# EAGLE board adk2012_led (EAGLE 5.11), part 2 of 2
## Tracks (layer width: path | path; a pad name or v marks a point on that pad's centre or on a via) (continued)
GND  (via drill 0.3) (continued)
  Top 0.508: v106.88,41.86 114.12,41.86 115.01,42.75 120.22,42.75 121.11,43.64 121.11,45.29 | 34.96,56.34 C20.2 33.52,56.49 C19.2 33.22,52.91 32.72,52.4 29.54,52.4 | 29.54,52.4 29.03,52.91 29.03,54.81 | 29.03,54.81 29.03,55.91 U10.10 29.03,55.95 | U10.11 29.81,54.96 29.67,54.81 29.03,54.81 | U10.7 26.49,57.23 25.73,56.46 25.13,56.46 C22.2 25.1,55.19 25.6,54.69 28.91,54.69 29.03,54.81 | U7.2 9.35,68.53 9.73,68.15 11.51,68.15 12.4,69.04 C23.2 12.41,69.93 | 9.47,53.42 8.97,53.92 U8.7 8.97,57.73 8.52,58.18 C26.2 | 9.47,53.42 11.38,53.42 12.01,54.05 12.01,54.77 C24.2 12.33,54.71 C25.2 | C30.2 87.83,34.75 88.34,34.24 v88.34,30.56 | C28.2 54.24,75.56 52.35,75.56 52.02,75.9 52.02,78.31 53.29,79.58 53.99,80.28 J1.6 53.99,89.42 v54.05,89.48 | v54.05,89.48 53.99,88.66 | v29.54,43 29.54,52.4 | v9.47,47.57 9.47,48.21 9.47,53.42 | J1.1 58.99,89.22 59,89.23 54.31,89.23 v54.05,89.48 | 128.6,80.85 128.6,79.45 129.43,78.63 130,78.63 132.22,78.63 132.47,78.88 C35.2 134.1,79.17 C36.2 | 128.6,80.85 U13.4 | 128.6,80.85 127.58,80.85 127.08,81.36 127.08,82.63 125.93,83.77 122.73,83.77 JP1.7 | C15.2 13.32,90.35 | C42.2 172.61,26.68 v172.29,26.37 | v0.84,70.43 1.98,70.43 v3.51,71.96 | v5.28,71.96 5.28,71.58 6.3,70.56 U7.EP
  Top 0.762: v183.21,41.73 183.21,43.03 183.24,43.03 C6.2 | v194.64,32.08 192.48,32.08 | 192.48,32.08 192.38,32.08 | v159.46,42.62 R1.1 | 183.46,26.24 v183.46,25.35 v182.58,25.35 183.46,26.24 | 183.46,26.24 v183.46,30.3 183.46,32.08 183.72,32.33 C4.2 | JP4.4 106.17,37.34 v106.88,38.05 | 15.2,90.98 15.84,91.62 17.88,91.62 C31.2 17.86,91.64 | 192.48,32.08 C8.2 | C10.2 192.86,43.89 193.12,43.89 v194.39,42.62
  Top 1.016: JP4.4 104.55,30.48 v104.47,30.56 | JP7.35 JP7.36 181.64,76.2 v181.69,76.15 | v121.87,88.34 122.68,87.53 JP1.7 122.63,83.77 121.23,83.77 120.14,82.68 JP1.6 | v161.87,36.65 161.87,34.5 C43.2 C44.2 161.81,26.81 v162.26,26.37 v163.14,26.37 v161.37,26.37
  Bottom 0.254: v194.39,42.62 194.13,42.88 191.08,42.88 190.32,43.64 190.32,50.62 v190.2,50.75 | v122,47.57 123.01,47.57 v124.28,46.3 | v98.88,48.08 98.88,46.69 100.03,45.54 105.49,45.54 106.25,44.78 v106.88,44.78 | v9.86,94.18 U11.EP@6
  Bottom 0.381: v47.83,54.18 43.64,54.18 43,53.54 v41.22,53.54
  Bottom 0.406: 193.62,94.06 196.16,94.06 | 196.16,94.06 198.07,94.06 198.32,93.8 U9.2 | 196.16,94.06 C27.2
  Bottom 0.508: v88.34,30.56 88.21,30.59 82.94,30.53 | 54.81,94.31 54.05,93.55 v54.05,89.48 | v29.54,43 29.54,43.03 29.56,42.79 | v9.47,47.57 9.47,47.32 9.49,47.45 | 0.84,89.36 v2.24,89.36 | v3.51,71.96 v5.28,71.96
  Bottom 0.762: 180.67,94.06 180.67,94.31 | 180.67,94.31 193.37,94.31 193.62,94.06 | 206.71,87.07 207.59,86.18 207.59,32.08 204.55,29.03 | 54.81,94.31 121.87,94.31 180.67,94.31 | v183.46,30.3 183.46,41.48 v183.21,41.73 | v194.39,42.62 194.64,42.37 v194.64,32.08 194.64,29.03 190.96,25.35 v183.46,25.35 v182.58,25.35 176.61,25.35 175.59,26.37 | v161.87,36.65 161.62,36.65 159.46,38.81 v159.46,42.62 | v106.88,44.78 v106.88,41.86 v106.88,38.05
  Bottom 0.889: 193.62,94.06 193.62,91.39 | 9.49,47.45 0.84,49.48 v0.84,70.43 0.84,89.36 0.84,94.18 v9.86,94.18 | 121.87,94.31 v121.87,88.34 | 180.67,88.72 180.67,94.06
  Bottom 1.016: v181.69,76.15 181.69,82.63 181.56,82.75 181.56,87.83 180.67,88.72 | 193.62,91.39 197.94,87.07 206.71,87.07 | 9.49,47.45 29.56,42.79 30.43,42.59 82.94,30.53 104.24,30.53 v104.47,30.56 108.66,26.37 v161.37,26.37 v162.26,26.37 v163.14,26.37 v172.29,26.37 175.59,26.37 | 204.55,29.03 194.64,29.03
  other vias: 6.68,92.15 6.68,94.18 30.81,94.18 13.03,94.18 16.21,94.18 19.38,94.18 23.06,94.18 27.25,94.18 9.86,92.15 23.06,86.69 27.25,86.69 30.81,86.69
  pour Top (isolate 0.762): 52.78,85.42 60.27,85.42 60.27,89.74 52.78,89.74
  pour Bottom (isolate 0.381, no thermals): 8.97,87.96 6.17,90.75 6.17,94.44 6.3,94.56 34.87,94.56 34.87,87.45 33.73,86.18 15.7,86.18 14.05,87.96
  pour Top (isolate 0.381, no thermals): 6.3,94.69 6.3,90.88 10.24,86.94 14.94,86.94 15.7,86.18 33.73,86.18 34.87,87.45 34.87,94.69
INT  (via drill 0.3)
  Top 0.254: U14.15 122.39,50.13 123.39,51.13 126.7,51.13 128.47,49.35 v131.78,49.35 133.05,49.35 133.43,48.97 133.43,48.18 R41.1 | U12.15 53.66,71.82 v52.91,71.07 | v201.12,90.5 201.12,88.21 207.21,82.12 207.21,54.05 v206.45,53.29 | v198.32,53.29 191.21,53.29 189.31,55.19 186.51,55.19 185.62,54.31 183.72,54.31 181.69,52.27 181.69,51.77 180.72,50.8 JP7.16 177.85,50.88 v174.83,50.88 | v53.67,41.1 53.67,40.46 75.01,35.64 84.15,35.64 84.91,34.87 v84.91,33.35 | v133.93,28.78 v133.93,34.87 v133.93,36.4
  Bottom 0.254: v174.83,50.88 174.83,38.05 171.65,34.87 v133.93,34.87 | v52.91,71.07 57.23,66.75 57.23,48.72 53.67,45.16 v53.67,41.1 | v206.45,53.29 v198.32,53.29 | v84.91,33.35 85.04,33.22 106.63,33.22 111.33,28.52 122.25,28.52 122.5,28.78 v133.93,28.78 | v133.93,36.4 133.93,47.19 v131.78,49.35 | U9.4 200.52,91.1 v201.12,90.5
MOSI  (via drill 0.3)
  Top 0.254: U1.32 157.64,47.11 158.06,46.69 163.91,46.69 166.19,44.4 v179.65,44.4 | JP7.32 181.86,71.12 v181.94,71.2
  Bottom 0.254: v181.94,71.2 181.94,60.02 183.21,58.75 183.21,54.43 179.65,50.88 v179.65,44.4
N$1  (via drill 0.3)
  Top 0.254: U1.25 153.9,46.46 152.86,45.42 v152.86,44.91 | U2.32 108.24,48.5 109.68,47.07 v109.68,46.56
  Bottom 0.254: v152.86,44.91 152.86,39.32 149.3,35.64 130.76,35.64 129.87,34.75 125.68,34.75 124.66,35.76 111.71,35.76 109.68,37.8 v109.68,46.56
N$2
  Top 0.254: R2.2 101.8,48.08 101.8,47.7 102.69,46.81 103.84,46.81 104.72,47.7 104.72,48.49 U2.27
N$3
  Top 0.254: R3.2 188.42,37.88 188.42,36.78 188.63,36.57 D65.C 188.67,35.85 188.67,35.26 188.48,35.06 Q1.1 188.56,34.11 189.31,34.11 189.67,33.75 C3.2
N$5
  Top 0.254: U1.27 154.9,45.81 154.64,45.54 154.64,43.55 155.56,42.62 R1.2
N$6
  Top 0.254: C5.2 189.62,44.97 189.31,45.29 188.82,45.29 Q2.1 188.48,46.49 188.67,46.69 188.67,47.28 D66.C 188.67,47.36 188.67,48.21 188.27,48.62 R5.2
N$7
  Top 0.254: R7.2 197.05,37.88 197.05,36.91 197.26,36.7 D67.C 197.31,35.85 197.31,35.26 197.11,35.06 Q3.1 197.2,34.11 197.94,34.11 198.31,33.75 C7.2
N$8
  Top 0.254: U10.12 30.61,54.87 30.05,54.31 30.05,53.71 C21.1
N$9
  Top 0.254: U10.13 31.41,54.72 31.7,54.43 31.7,53.71 C21.2
N$11
  Top 0.254: C22.1 25.69,58.08 26.24,58.62 27.32,58.62 U10.6
N$12
  Top 0.254: R9.2 196.9,48.62 197.31,48.21 197.31,47.36 D68.C 197.26,46.77 197.05,46.56 197.05,45.69 Q4.1 197.33,45.42 197.94,45.42 198.39,44.97 C9.2
N$13
  Top 0.254: R11.1 6.68,83.39 6.43,83.64 6.43,88.98 6.74,89.29 U11.3
N$14
  Top 0.254: U11.4 7.61,88.64 7.32,88.34 7.32,85.59 R12.1
N$15
  Top 0.254: R11.2 C17.1
N$16
  Top 0.254: R12.2 C18.1
N$17  (via drill 0.3)
  Top 0.254: U12.14 52.71,72.27 v52.27,71.83 | v52.78,40.46 52.78,40.08 74.88,35 81.48,35 | 81.48,35 83.39,35 v83.77,34.62 | U15.5 88.93,35.69 v89.36,35.26 | R46.1 81.55,34.94 81.48,35
  Bottom 0.254: v52.27,71.83 52.27,70.69 56.59,66.37 56.59,48.97 52.78,45.16 v52.78,40.46 | v89.36,35.26 84.4,35.26 v83.77,34.62
N$18
  Top 0.381: U11.8 11.72,90.59 12.01,90.88 12.01,91.64 13.41,93.04 20.52,93.04 21.45,92.11 FB5.1
N$19  (via drill 0.3)
  Top 0.254: 80.47,36.53 74.12,36.53 54.56,40.84 v54.56,41.73 | 80.47,36.53 U15.4 | v53.42,74.24 53.92,74.24 54.56,73.61 55.16,73.61 U12.11 | 80.47,36.53 R45.1
  Bottom 0.254: v54.56,41.73 54.56,45.03 57.86,48.34 57.86,67.26 53.42,71.7 v53.42,74.24
N$20
  Top 0.381: U11.5 11.72,88.64 12.9,87.45 15.7,87.45 16.71,86.44 19.89,86.44 21.45,88 FB6.1
N$21
  Top 0.254: J1.2 57.99,83.14 57.35,82.5 57.35,81.36 58.75,79.96 58.77,78.31 R23.1
  Top 0.406: J1.2 57.99,87.04 57.38,87.66 55.6,87.66 54.97,87.02 54.97,85.52 J1.5
N$22
  Top 0.254: J1.3 56.99,83.41 56.46,82.88 R24.1
N$23  (via drill 0.3)
  Top 0.254: U12.9 56.27,74.84 C28.1 55.58,75.53 55.58,76.53 | FB1.1 55.03,77.08 55.58,76.53 | v55.96,76.91 55.58,76.53 | v52.27,74.24 52.27,73.12 R13.2
  Bottom 0.254: v55.96,76.91 54.43,76.91 52.27,74.75 v52.27,74.24
N$24
  Bottom 0.406: U9.3 198.97,92.39 199.21,92.15 D69.2
N$25
  Top 0.254: J1.4 55.99,84.06 55.07,83.13 R25.1
N$26
  Top 0.254: U12.12 54.12,73.17 54.05,73.1 R13.1
N$27
  Top 0.254: U14.9 120.8,46.62 121.11,46.3 C29.1 | R26.2 126.82,49.35 127.97,48.21 130,48.21 130.51,47.7 130.51,46.81 130.12,46.43 127.97,46.43 127.2,47.19 126.23,47.19 FB2.1
  Top 0.305: FB2.1 125.59,47.15 125.17,47.57 123.25,47.57 122.31,46.64 C29.1
N$28
  Top 0.254: U12.5 58.27,75.92 58.75,76.4 R23.2
N$29
  Top 0.254: U12.7 57.17,78.11 55.07,80.21 R25.2
N$30
  Top 0.254: U12.6 57.62,79.06 56.46,80.21 R24.2
N$32
  Top 0.508: J2.2 39.95,86.53 39.95,86.82 | 39.95,86.82 TP2.TP | 39.95,86.82 39.95,88.6 39.45,89.1 32.4,89.1 31.38,90.12 27,90.12 25.54,88.66 C33.1 23.6,88.66 FB6.2
N$33
  Top 0.254: U14.12 122.94,48.78 123.52,49.35 R26.1
N$34  (via drill 0.3)
  Top 0.254: U14.14 122.57,49.68 123.52,50.62 126.31,50.62 128.22,48.72 v130.63,48.72 | v113.36,40.34 113.11,40.08 97.36,40.08 96.22,38.94 91.26,38.94 89.87,40.34 U15.8 88.34,40.34 87.96,40.72 R44.1
  Bottom 0.254: v130.63,48.72 130.63,36.4 129.62,35.38 125.68,35.38 124.79,36.27 113.87,36.27 113.36,36.78 v113.36,40.34
N$35  (via drill 0.3)
  Top 0.254: U14.11 123.13,48.33 123.27,48.34 126.95,48.34 127.97,47.32 v129.74,47.32 | v114,39.57 97.49,39.57 96.34,38.43 90.75,38.43 90.12,39.07 U15.7 88.09,39.07 86.06,41.1 R43.1
  Bottom 0.254: v129.74,47.32 129.74,36.4 129.24,35.89 125.81,35.89 124.92,36.78 114.38,36.78 114,37.16 v114,39.57
N$36
  Top 0.254: U12.4 58.82,73.17 59,73.36 59,75.77 59.39,76.15 60.15,76.15 60.4,76.4 R22.2
N$37  (via drill 0.3)
  Top 0.254: v58.24,82.12 60.4,79.96 R22.1 60.4,78.31
  Bottom 0.254: P1.P$1 50.37,82.12 v58.24,82.12
  pour Bottom (isolate 1.016, no thermals): 50.37,83.39 39.95,83.39 39.95,73.1 50.37,73.1
N$38  (via drill 0.3)
  Top 0.254: v51.77,90.37 52.27,90.88 60.15,90.88 61.42,89.61 61.42,75.25 61.05,74.88 R21.1
  Bottom 0.254: P2.P$1 38.05,82.88 39.83,84.66 50.75,84.66 51.77,85.67 v51.77,90.37
  pour Bottom (isolate 1.016, no thermals): 37.8,83.39 27.38,83.39 27.38,73.1 37.8,73.1
N$39
  Top 0.254: U12.3 59,72.72 59.51,73.23 59.51,74.51 R21.2
N$40
  Top 0.254: U12.2 59.43,72.27 R20.2
N$41
  Top 0.254: U12.16 54.03,71.17 52.78,69.93 R14.2
N$42  (via drill 0.3)
  Top 0.254: v79.71,48.97 93.8,48.97 96.85,45.92 101.68,45.92 103.96,43.64 113.23,43.64 114.76,45.16 R36.1
  Bottom 0.254: P12.P$1 83.26,75.01 79.71,71.45 v79.71,48.97
  pour Bottom (isolate 0.254, no thermals): 94.95,84.66 84.53,84.66 84.53,74.37 94.95,74.37
N$43  (via drill 0.3)
  Top 0.254: U14.16 121.25,51.01 121.62,51.38 v122.5,51.38 | v124.79,44.78 122.38,44.78 122.12,44.53 R27.2
  Bottom 0.254: v122.5,51.38 124.79,51.38 125.04,51.13 125.04,45.03 v124.79,44.78
N$44  (via drill 0.3)
  Top 0.254: v186.39,30.68 186.39,24.21 184.1,21.92 176.48,21.92 175.72,22.68 132.79,22.68 128.6,26.87 v128.6,36.65 | R27.1 122.12,42.24 123.01,41.35 v128.6,41.35
  Bottom 0.254: P21.P$1 188.16,55.58 186.39,53.8 v186.39,30.68 | v128.6,36.65 v128.6,41.35
  pour Bottom (isolate 0.254, no thermals): 187.66,69.42 198.07,69.42 198.07,59.13 187.66,59.13
N$45
  Top 0.254: U14.5 118.8,47.93 117.42,46.56 117.42,45.42 117.17,45.16 R36.2
N$46  (via drill 0.3)
  Top 0.254: v77.8,47.96 93.8,47.96 96.47,45.29 101.55,45.29 103.71,43.13 113.74,43.13 114.63,44.02 116.92,44.02 117.62,44.72 R37.1
  Bottom 0.254: P11.P$1 71.96,75.01 73.1,73.86 75.64,73.86 77.8,71.7 v77.8,47.96
  pour Bottom (isolate 0.254, no thermals): 72.59,84.66 62.18,84.66 62.18,74.37 72.59,74.37
N$47  (via drill 0.3)
  Top 0.254: v76.66,46.94 93.8,46.94 96.22,44.53 101.55,44.53 103.45,42.62 114,42.62 114.76,43.38 119.46,43.38 119.84,43.76 R38.1
  Bottom 0.254: v76.66,46.94 76.66,55.19 72.09,59.77 P10.P$1
  pour Bottom (isolate 0.254, no thermals): 72.59,69.42 62.18,69.42 62.18,59.13 72.59,59.13
N$48
  Top 0.254: U14.7 119.9,45.5 R38.2
N$49
  Top 0.254: U14.6 119.45,47.06 119.33,46.94 118.57,46.94 118.31,46.69 R37.2
N$50
  Top 0.254: U14.4 118.24,48.78 117.93,48.46 117.93,47.7 117.04,46.81 R35.2
N$51  (via drill 0.3)
  Top 0.254: v81.61,49.86 93.8,49.86 97.1,46.56 101.93,46.56 104.34,44.15 111.96,44.15 114.63,46.81 R35.1
  Bottom 0.254: P13.P$1 82.63,57.35 82.63,50.88 v81.61,49.86
  pour Bottom (isolate 0.254, no thermals): 94.82,69.42 84.4,69.42 84.4,59.13 94.82,59.13
N$52  (via drill 0.3)
  Top 0.254: v114,48.59 R34.1
  Bottom 0.254: P14.P$1 114.25,73.86 108.15,67.77 108.15,64.21 112.47,59.89 112.47,58.75 114,57.23 v114,48.59
  pour Bottom (isolate 0.254, no thermals): 124.16,84.66 113.74,84.66 113.74,74.37 124.16,74.37
N$53
  Top 0.254: U14.3 117.93,49.23 117.3,48.59 R34.2
N$54
  Top 0.508: P9.P$1 R14.1
N$55
  Top 0.254: U12.1 58.76,71.82 59.26,71.32 R19.2
N$56
  Top 0.254: U12.20 57.89,71.17 59.89,69.16 R18.2
N$57
  Top 0.254: U12.19 57.17,70.49 58.12,69.55 R17.2
N$58  (via drill 0.3)
  Top 0.254: v53.54,62.94 53.54,63.58 56.34,66.37 R16.1
  Bottom 0.254: P7.P$1 39.45,58.88 50.75,58.88 52.27,60.4 52.27,62.43 52.78,62.94 v53.54,62.94
  pour Bottom (isolate 1.016, no thermals): 37.8,70.82 27.38,70.82 27.38,60.53 37.8,60.53
N$59  (via drill 0.3)
  Top 0.254: v53.54,59.89 53.54,61.54 56.08,64.08 56.08,64.85 58.12,66.88 R17.1
  Bottom 0.254: P6.P$1 24.59,61.04 21.16,61.04 21.16,58.24 22.05,57.35 51,57.35 v53.54,59.89
  pour Bottom (isolate 1.016, no thermals): 25.35,70.82 14.94,70.82 14.94,60.53 25.35,60.53
N$60  (via drill 0.3)
  Top 0.254: v53.54,57.86 54.94,59.26 54.94,61.04 57.1,63.2 57.1,64.47 59.89,67.26 R18.1 59.89,67.51
  Bottom 0.254: P5.P$1 11.51,58.24 13.92,55.83 51.51,55.83 v53.54,57.86
  pour Bottom (isolate 1.016, no thermals): 12.9,70.82 2.49,70.82 2.49,60.53 12.9,60.53
N$61  (via drill 0.3)
  Top 0.254: R19.1 62.05,71.32 64.34,73.61 64.34,91.64 63.32,92.66 51.13,92.66 49.73,91.26 49.73,81.99 49.35,81.61 15.82,81.61 15.32,81.1 v4.65,81.1
  Bottom 0.254: v4.65,81.1 P4.P$1
  pour Bottom (isolate 1.016, no thermals): 12.9,83.39 2.49,83.39 2.49,73.1 12.9,73.1
N$62  (via drill 0.3)
  Top 0.254: v17.22,80.85 49.86,80.85 50.5,81.48 50.5,90.88 51.38,91.77 61.29,91.77 62.94,90.12 62.94,74.48 61.56,73.1 R20.1
  Bottom 0.254: v17.22,80.85 P3.P$1
  pour Bottom (isolate 1.016, no thermals): 25.35,83.39 14.94,83.39 14.94,73.1 25.35,73.1
N$63
  Top 0.254: U12.18 56.72,69.8 56.34,69.42 R16.2
N$64
  Top 0.254: U12.17 56.27,70.49 54.56,68.78 R15.2
N$65  (via drill 0.3)
  Top 0.254: v52.27,64.97 53.67,64.97 54.56,65.86 R15.1 54.56,67.64
  Bottom 0.254: P8.P$1 v52.27,64.97
  pour Bottom (isolate 1.016, no thermals): 50.37,70.82 39.95,70.82 39.95,60.53 50.37,60.53
N$66
  Top 0.254: R33.2 117.04,49.68 U14.2
N$67
  Top 0.254: U14.1 118.3,50.13 116.92,51.51 R32.2
N$68
  Top 0.254: U14.20 119.45,52.5 R31.2
N$69
  Top 0.254: U14.19 119.9,51.7 123.14,54.94 R30.2
N$70  (via drill 0.3)
  Top 0.254: v164.92,43.13 164.92,41.61 163.4,40.08 v136.86,40.08 | R29.1 125.81,53.54 128.98,50.37 v136.86,50.37
  Bottom 0.254: P19.P$1 164.92,58.75 164.92,54.69 167.08,52.53 167.08,45.29 v164.92,43.13 | v136.86,40.08 v136.86,50.37
  pour Bottom (isolate 0.254, no thermals): 165.3,69.42 175.72,69.42 175.72,59.13 165.3,59.13
N$71  (via drill 0.3)
  Top 0.254: v163.02,44.15 163.02,41.86 162.51,41.35 v137.87,41.35 | R30.1 126.06,54.94 129.49,51.51 v137.87,51.51
  Bottom 0.254: P18.P$1 163.02,72.09 163.02,69.55 160.86,67.39 160.86,61.42 163.53,58.75 163.53,54.05 165.81,51.77 165.81,46.94 v163.02,44.15 | v137.87,41.35 v137.87,51.51
  pour Bottom (isolate 0.254, no thermals): 175.72,84.66 165.3,84.66 165.3,74.37 175.72,74.37
N$72  (via drill 0.3)
  Top 0.254: v136.6,57.73 135.46,56.59 123.65,56.59 120.66,53.61 R31.1
  Bottom 0.254: v136.6,57.73 P17.P$1
  pour Bottom (isolate 0.254, no thermals): 136.09,69.42 146.51,69.42 146.51,59.13 136.09,59.13
N$73  (via drill 0.3)
  Top 0.254: R32.1 116.92,54.43 117.42,54.94 120.98,54.94 124.03,57.99 v132.28,57.99
  Bottom 0.254: P16.P$1 131.52,69.93 131.52,63.07 132.28,62.31 v132.28,57.99
  pour Bottom (isolate 0.254, no thermals): 146.38,84.66 135.97,84.66 135.97,74.37 146.38,74.37
N$74  (via drill 0.3)
  Top 0.254: 115.25,51.75 v115.27,51.77 115.46,51.57 R33.1
  Bottom 0.254: v115.27,51.77 115.27,58.12 114.38,59 P15.P$1
  pour Bottom (isolate 0.254, no thermals): 113.74,69.42 124.16,69.42 124.16,59.13 113.74,59.13
N$75
  Top 0.254: U14.18 120.35,51.51 122.38,53.54 R29.2
N$76  (via drill 0.3)
  Top 0.254: U14.17 120.8,51.33 121.74,52.27 v123.77,52.27 | R28.2 124.97,43.57 v125.17,43.78
  Bottom 0.254: v123.77,52.27 125.04,52.27 125.55,51.77 125.55,44.16 v125.17,43.78
N$77  (via drill 0.3)
  Top 0.254: v184.86,30.18 184.86,24.33 183.72,23.19 177.11,23.19 176.35,23.95 134.7,23.95 131.65,27 v131.65,36.91 | v132.41,42.88 124.92,42.88 124.73,42.68 R28.1
  Bottom 0.254: P20.P$1 188.16,74.12 183.72,69.67 183.72,61.29 184.86,60.15 v184.86,30.18 | v132.41,42.88 132.41,37.67 v131.65,36.91
  pour Bottom (isolate 0.254, no thermals): 187.66,84.66 198.07,84.66 198.07,74.37 187.66,74.37
N$78  (via drill 0.3)
  Top 0.254: v189.18,51.89 188.54,52.53 187.66,52.53 187.08,51.96 C12.1 186.32,52.4 U4.5 | v190.32,40.21 189.81,40.72 187.4,40.72 187.08,40.4 C11.1 186.33,40.71 U3.5 | v193.37,41.99 193.76,41.59 U5.5 194.97,40.71 C13.1 | v189.18,54.18 190.7,52.65 193.24,52.65 193.76,52.14 U6.5 195.09,52.14 C14.1
  Top 0.508: Q2.2 186.17,45.63 185.24,46.56 183.74,46.56 | Q3.2 194.3,34.2 193.37,35.13 192.38,35.13 | Q4.2 194.81,45.63 193.62,46.81 192.46,46.81 | 192.27,46.76 192.27,46.62 | R10.2 192.35,49.33 C10.1 | R8.2 192.38,35.55 C8.1
  Top 0.762: 192.38,35.13 192.48,35.13 C8.1 192.42,35.19 v190.39,35.19 | 192.46,46.81 192.46,46.59 C10.1 192.29,46.62 192.27,46.62 | FB3.1 178,27.51 178.13,27.38 v179.27,27.38 v180.16,27.38 180.29,27.38 180.67,27.76 180.67,30.94 181.69,31.95 181.69,35.13 | 181.69,35.13 181.69,35.38 | 181.69,35.38 181.69,37.92 | 181.69,37.92 v181.69,39.7 | v181.81,46.56 183.72,46.56 C6.1 183.74,46.54 183.74,46.56 183.74,49.49 R6.2 | 181.69,37.92 R4.2 | 181.69,35.13 | Q1.2 185.64,35.13 C4.1 181.75,35.45 181.69,35.38 | v190.39,35.19 | 192.27,46.76 189.61,46.76 v189.56,46.81
  Bottom 0.254: 190.32,41.99 v193.37,41.99 | v189.18,51.89 v189.18,54.18
  Bottom 0.762: v181.69,39.7 181.69,46.43 v181.81,46.56 | v179.27,27.38 v180.16,27.38 188.67,27.38 191.08,29.79 191.08,34.49 v190.39,35.19 190.32,35.26 v190.32,40.21 190.32,41.99 189.56,42.75 v189.56,46.81 189.56,49.48 189.18,49.86 v189.18,51.89
N$79
  Top 0.508: TP1.TP 41.47,86.82 J2.1 41.47,92.54 40.08,93.93 33.99,93.93 31.45,91.39 26.49,91.39 25.41,92.47 C32.1 23.6,92.47 FB5.2
N$80  (via drill 0.3)
  Top 0.254: U11.1 6.13,90.59 5.54,89.99 v5.54,88.72
  Top 0.305: U11.6 12.21,89.29 12.33,89.17 C15.1
  Top 0.508: C15.1 C16.1 15,88.72 v15.95,88.72
  Top 0.762: 15.47,88.72 v15.95,88.72 16.65,88.02 C31.1
  Top 0.889: FB4.1 5.5,88.68 v5.54,88.72
  Bottom 0.889: v5.54,88.72 6.68,88.72 8.46,86.94 14.17,86.94 14.43,87.2
  Bottom 1.016: 14.43,87.2 v15.95,88.72
N$82
  Top 0.254: R40.2 133.44,83.72 | U13.1 133.63,81.18 133.68,81.23 | 133.68,81.23 133.68,83.48 R40.2 | 133.68,81.23 135.59,81.23 136.73,80.09 136.73,76.78 132.79,72.85 123.77,72.85 122.63,73.99 116.66,73.99 116.28,74.37 68.66,74.37 65.61,77.42 65.61,92.53 64.47,93.68 49.99,93.68 48.34,92.02 48.34,83.9 47.19,82.75 12.86,82.75 C17.2 | C45.1 133.24,84.85 133.53,84.56 R40.2
N$83
  Top 0.254: U13.2 131.14,82.12 130.51,82.75 130.51,83.48 R42.2 R40.1 | R40.1 132.14,83.72 | C45.2 132.35,84.85 132.05,84.56 R40.1
SCL  (via drill 0.3)
  Top 0.254: v200.1,89.99 200.1,88.6 206.71,81.99 206.71,58.12 205.69,57.1 205.69,48.34 206.71,47.32 206.71,20.52 201.24,15.06 197.94,15.06 195.78,17.22 169.24,17.22 168.35,16.33 159.59,16.33 157.56,18.36 133.81,18.36 115.27,22.81 100.41,26.49 98.5,28.4 98.5,35.51 JP4.1 98.55,36.98 98.25,37.29 91.52,37.29 90.88,36.65 v90.5,36.65 | v85.29,40.34 U15.1 64.85,40.34 56.85,42.11 55.45,43.51 52.08,43.51 v50.26,41.69 | U10.2 30.61,59.84 30.3,60.15 23.95,60.15 23.06,59.26 23.06,48.46 v22.95,47.98 | U8.5 v5.92,56.21 3.63,56.21 1.98,57.86 1.98,67.77 4.39,70.18 4.39,72.34 4.9,72.85 5.66,72.85 6.43,72.09 8.32,72.09 U7.6
  Bottom 0.254: v200.1,89.99 199.85,90.25 198.58,90.25 198.32,90.5 U9.5 | v90.5,36.65 86.82,40.34 v85.29,40.34 | v50.26,41.69 v22.95,47.98 8.2,51.38 5.92,52.02 v5.92,56.21
SCLK  (via drill 0.3)
  Top 0.254: U1.31 156.9,46.45 157.18,46.18 158.32,46.18 158.45,46.05 163.91,46.05 166.7,43.26 v167.59,43.26 168.99,41.86 v180.8,41.86 | U2.31 106.74,47.59 107.01,47.32 108.28,47.32 108.92,46.69 v108.92,45.67 | JP7.33 173.74,73.66 174.96,74.88 v183.08,74.88 | v108.92,40.84 109.17,41.1 113.74,41.1 115.27,39.57 120.73,39.57 121.74,38.56 164.54,38.56 v166.83,40.84
  Bottom 0.254: v183.08,74.88 183.08,70.31 182.96,70.18 182.96,60.4 184.23,59.13 184.23,54.05 180.92,50.75 180.92,41.99 v180.8,41.86 | v108.92,40.84 v108.92,45.67 | v167.59,43.26 166.83,42.49 v166.83,40.84
SDA  (via drill 0.3)
  Top 0.254: v199.21,89.36 199.21,88.85 206.2,81.86 206.2,58.24 205.18,57.23 205.18,48.21 206.2,47.19 206.2,20.78 200.99,15.57 198.2,15.57 196.04,17.73 168.99,17.73 168.1,16.84 159.72,16.84 157.68,18.87 134.32,18.87 101.3,26.87 101.3,27.89 101.04,28.14 101.04,30.43 JP4.2 101.09,38.51 100.53,39.07 97.61,39.07 96.47,37.92 90.37,37.92 89.87,38.43 87.83,38.43 87.2,39.07 U15.2 82.12,39.07 81.61,39.57 64.72,39.57 56.46,41.48 55.07,42.88 53.42,42.88 v51.13,40.59 | U10.3 29.81,59.49 29.67,59.64 24.33,59.64 23.57,58.88 23.57,49.1 23.95,48.72 23.95,47.19 v23.84,46.69 | U7.1 8.32,69.04 4.52,69.04 3.12,67.64 3.12,57.61 3.76,56.97 v4.9,56.97 | v4.9,54.69 7.29,54.69 U8.6
  Bottom 0.254: v4.9,56.97 v4.9,54.69 4.9,51.13 7.32,50.5 v23.84,46.69 50.88,40.46 v51.13,40.59 | U9.6 197.67,90.39 198.7,89.36 v199.21,89.36
VLED_BANK0  (via drill 0.3)
  Top 0.254: Q1.3 188.59,32 189.18,32.59 189.67,32.59 C3.1
  Top 0.381: 53.67,49.48 53.66,49.49 | C37.1 53.48,49.48 53.42,49.48
  Top 0.406: v43.76,67.26 v43.76,76.53 | v43.76,64.08 46.69,61.16 46.69,53.67 50.88,49.48 53.42,49.48 53.67,49.48 70.56,49.48 74.24,45.8 92.41,45.8 95.71,42.49 102.57,42.49 103.07,41.99 103.58,41.99 v103.71,41.86
  Top 0.508: Q1.3 v187.53,29.16 195.91,29.16 v197.56,30.81 | v120.22,34.37 v120.22,38.81
  Bottom 0.406: D1.1 193.74,87.85 D1.2 193.74,86.55 D1.3 | D6.1 199.83,81.09 D6.2 201.13,81.09 D6.3 | D2.3 184.47,79.59 D2.2 185.77,79.59 D2.1 | D7.3 192.24,72.48 D7.2 192.24,71.18 D7.1 | D5.1 199.83,65.47 D5.2 201.13,65.47 D5.3 | D3.1 184.47,65.47 D3.2 185.77,65.47 D3.3 | D4.1 193.74,57.24 D4.2 193.74,55.94 D4.3 | D8.1 119.83,87.85 D8.2 119.83,86.55 D8.3 | D13.3 126.05,79.59 D13.2 127.35,79.59 D13.1 | D9.1 111.98,79.59 D9.2 110.68,79.59 D9.3 | D14.1 118.33,71.18 D14.2 118.33,72.48 D14.3 118.43,72.58 | D10.1 111.98,63.97 D10.2 110.68,63.97 D10.3 | D12.1 127.22,63.97 D12.2 125.92,63.97 D12.3 | D11.3 118.33,57.24 D11.2 118.33,55.94 D11.1 118.44,55.83 | 126.38,72.4 126.7,72.72 | D15.3 44.41,78.7 D15.2 44.41,77.4 D15.1 43.76,76.56 v43.76,76.53 | v43.76,67.26 44.51,66.36 D16.3 44.41,66.26 D16.2 44.41,64.96 D16.1 44.51,64.83 v43.76,64.08
  Bottom 0.508: D1.2 195.4,87.2 197.18,85.42 198.7,85.42 198.96,85.17 198.96,83.52 200.48,81.99 D6.2 | D2.1 186.64,80.46 186.64,81.61 185.75,82.5 185.75,85.55 187.4,87.2 189.94,87.2 191.47,85.67 192.87,85.67 D1.3 | D6.3 201.23,80.99 202.13,80.09 202.13,73.23 200.48,71.58 | 200.48,71.58 197.69,71.58 195.78,73.48 193.24,73.48 D7.3 | 200.48,71.58 D5.2 | D3.2 185.12,69.42 187.53,71.83 D7.2 | D5.3 201.23,65.37 202.01,64.59 202.01,59.26 199.34,56.59 D4.2 | D8.2 123.39,87.2 125.3,89.1 127.08,89.1 128.09,88.09 128.09,81.74 128.22,81.61 128.22,80.46 D13.1 | 118.43,72.58 119.33,73.48 121.36,73.48 123.01,71.83 125.81,71.83 126.38,72.4 128.09,70.69 128.09,64.85 127.32,64.07 D12.1 | 126.7,72.72 D13.2 | D8.3 119.73,86.2 119.2,85.67 117.42,85.67 115.9,87.2 112.98,87.2 112.09,86.31 112.09,82.63 112.85,81.86 112.85,80.46 D9.1 | D10.3 110.58,64.07 109.42,65.23 109.42,66.75 114.5,71.83 D14.2 | D12.2 126.57,61.93 125.17,60.53 125.17,57.48 124.41,56.72 123.77,56.72 | 123.77,56.72 122.76,56.72 121.23,58.24 119.33,58.24 D11.3 | v120.22,38.81 120.22,50.88 123.65,54.31 123.65,56.59 123.77,56.72 | D4.3 193.64,55.81 197.56,51.89 v197.56,30.81 | v103.71,41.86 103.71,38.05 105.36,36.4 108.66,36.4 110.44,34.62 119.96,34.62 v120.22,34.37 121.62,32.97 124.92,32.97 126.31,31.57 165.05,31.57 165.56,31.06 179.53,31.06 181.43,29.16 v187.53,29.16
VLED_BANK1  (via drill 0.3)
  Top 0.254: Q2.3 187.57,43.38 188.54,43.38 189.24,44.08 C5.1
  Top 0.381: 45.67,54.69 C38.1
  Top 0.406: v31.32,67.39 v31.32,76.53 | v31.19,64.08 31.95,63.32 42.88,63.32 45.67,60.53 45.67,54.69 45.67,53.54 50.75,48.46 70.43,48.46 73.86,45.03 v80.47,45.03
  Top 0.508: v81.23,57.73 v85.04,57.73 | v80.47,45.03 92.15,45.03 95.45,41.73 102.18,41.73 v102.82,41.1 | v164.16,59.26 164.16,57.99 164.41,57.73 v165.81,57.73 | v167.34,30.3 167.34,39.57 v167.46,39.7 | v188.29,41.99 187.53,42.75 Q2.3
  Bottom 0.406: D17.1 171.39,87.85 D17.2 171.39,86.55 D17.3 | D18.3 162.24,79.59 D18.2 163.54,79.59 D18.1 | D22.1 178.91,79.59 D22.2 177.61,79.59 D22.3 | D23.3 169.89,72.48 D23.2 169.89,71.18 D23.1 | D21.3 177.48,63.97 D21.2 178.78,63.97 D21.1 | D20.3 169.89,57.24 D20.2 169.89,55.94 D20.1 | D19.1 162.24,65.47 D19.2 163.54,65.47 D19.3 | D24.1 90.62,87.85 D24.2 90.62,86.55 D24.3 | D25.3 81.34,79.59 D25.2 82.64,79.59 D25.1 | D30.3 89.12,72.48 D30.2 89.12,71.18 D30.1 | D29.3 96.71,79.59 D29.2 98.01,79.59 D29.1 | D26.3 81.34,63.97 D26.2 82.64,63.97 D26.1 | D27.3 89.12,57.24 D27.2 89.12,55.94 D27.1 | D28.1 98.01,63.97 D28.2 96.71,63.97 D28.3 | D31.3 31.84,78.7 D31.2 31.84,77.4 D31.1 31.94,77.28 v31.32,76.53 | v31.32,67.39 D32.3 31.84,66.26 D32.2 31.84,64.96 D32.1 31.94,64.83 v31.19,64.08
  Bottom 0.508: D17.2 174.83,87.2 176.86,89.23 178.51,89.23 180.16,87.58 180.16,80.85 D22.1 | D17.3 171.28,86.45 170.51,85.67 169.24,85.67 167.72,87.2 164.67,87.2 163.27,85.8 163.27,83.39 164.41,82.25 164.41,80.46 D18.1 | 166.95,71.83 D23.2 | 166.95,71.83 166.7,72.09 166.7,73.1 167.46,73.86 171.65,73.86 172.29,73.23 177.24,73.23 178.26,74.24 D22.2 | D21.2 178.13,57.99 177.37,57.23 173.3,57.23 172.42,58.12 170.76,58.12 D20.3 166.94,57.34 166.76,57.16 | D19.2 162.89,67.26 164.16,68.53 164.16,70.05 165.94,71.83 166.95,71.83 | D24.3 90.52,86.32 89.87,85.67 88.21,85.67 86.69,87.2 83.77,87.2 82.88,86.31 82.88,82.63 83.52,81.99 83.52,80.46 D25.1 | D24.2 93.42,87.2 97.1,90.88 98.5,90.88 99.26,90.12 99.26,80.85 D29.1 | D29.2 97.36,74.12 95.71,72.47 93.04,72.47 92.02,73.48 90.12,73.48 D30.3 | D26.1 82.74,64.07 83.64,64.97 83.64,67.89 82.75,68.78 82.75,70.82 83.77,71.83 D30.2 | D26.2 81.99,58.5 v81.23,57.73 80.59,57.1 80.59,45.16 v80.47,45.03 | v85.04,57.73 86.18,56.59 D27.2 | D28.2 97.36,59.13 95.58,57.35 93.42,57.35 92.53,58.24 90.12,58.24 D27.3 | 166.76,57.16 166.32,56.72 166.32,55.32 168.61,53.04 168.61,40.84 v167.46,39.7 | D19.3 163.64,65.37 164.41,64.59 164.41,59.51 v164.16,59.26 | v165.81,57.73 166.19,57.73 166.76,57.16 | v102.82,41.1 102.82,37.8 104.98,35.64 108.28,35.64 110.06,33.86 118.95,33.86 120.6,32.21 124.54,32.21 125.93,30.81 164.54,30.81 165.05,30.3 v167.34,30.3 178.77,30.3 180.8,28.27 187.91,28.27 189.18,29.54 189.18,40.84 188.29,41.73 v188.29,41.99
VLED_BANK2  (via drill 0.3)
  Top 0.254: Q3.3 197.1,32 197.69,32.59 198.44,32.59 C7.1
  Top 0.381: v18.87,52.65 18.87,48.73 C39.1
  Top 0.406: v18.87,67.13 v18.87,76.53 | v66.75,47.57 50.24,47.57 v44.91,52.91 | v18.62,63.96 18.87,63.7 v18.87,52.65
  Top 0.508: v66.75,47.57 70.18,47.57 73.48,44.27 91.9,44.27 95.33,40.84 v101.68,40.84 | v139.27,29.79 v139.27,36.78 | v193.62,30.43 195.66,30.43 196.16,30.94 Q3.3
  Bottom 0.406: 66.85,86.44 D40.1 66.76,86.55 D40.2 66.76,87.85 D40.3 | 60.53,65.35 D42.3 60.42,65.47 D42.2 59.12,65.47 D42.1 | D33.1 142.18,87.85 D33.2 142.18,86.55 D33.3 | D34.3 133.03,79.59 D34.2 134.33,79.59 D34.1 | D38.3 148.27,79.59 D38.2 149.57,79.59 D38.1 | D39.3 140.68,72.48 D39.2 140.68,71.18 D39.1 | D35.3 132.9,63.97 D35.2 134.2,63.97 D35.1 | D37.3 148.27,63.97 D37.2 149.57,63.97 D37.1 | D36.3 140.68,57.24 D36.2 140.68,55.94 D36.1 | D41.3 59.24,79.72 D41.2 60.54,79.72 D41.1 | D46.1 66.76,71.18 D46.2 66.76,72.48 D46.3 arc45 66.87,72.58 | D43.3 66.76,57.24 D43.2 66.76,55.94 D43.1 | D44.3 74.48,63.97 D44.2 75.78,63.97 D44.1 | D45.3 arc45 74.62,79.59 D45.2 75.64,79.59 arc45 D45.1 | D47.3 19.39,78.7 D47.2 19.39,77.4 D47.1 19.49,77.28 v18.87,76.53 | v18.87,67.13 18.87,66.98 D48.3 19.39,66.26 D48.2 19.39,64.96 D48.1 19.49,64.83 v18.62,63.96 | v18.87,52.65 44.02,52.65 44.27,52.91 v44.91,52.91
  Bottom 0.508: D33.2 147.02,87.2 148.54,85.67 148.54,82.88 147.4,81.74 147.4,80.46 D38.3 | D38.2 148.92,73.74 147.9,72.72 | 147.9,72.72 144.35,72.72 143.59,73.48 141.68,73.48 141.55,73.36 D39.3 | D34.1 135.2,80.46 135.2,81.74 133.81,83.13 133.81,86.31 134.7,87.2 137.74,87.2 139.27,85.67 141.3,85.67 142.07,86.45 D33.3 | D35.1 134.43,64.07 135.2,64.85 135.2,66.75 133.93,68.02 133.93,69.93 135.84,71.83 D39.2 | D37.3 148.05,64.07 147.4,64.72 147.4,68.53 147.9,69.04 147.9,72.72 | D35.2 133.55,57.99 134.95,56.59 D36.2 | D40.2 61.67,87.2 60.78,86.31 60.78,82.5 61.42,81.86 61.42,80.59 D41.1 | 61.42,71.83 D46.2 | 61.42,71.83 59.89,73.36 D41.2 | D42.2 59.77,67.77 61.42,69.42 61.42,71.83 | 66.87,72.58 67.77,73.48 69.67,73.48 71.32,71.83 75.39,71.83 76.78,70.43 76.78,64.97 D44.1 | D40.1 66.87,86.45 67.77,85.55 69.16,85.55 70.82,87.2 73.86,87.2 74.75,86.31 74.75,83.01 73.48,81.74 73.48,80.59 D45.3 | 60.53,65.35 60.91,65.35 61.29,64.97 61.29,61.04 60.78,60.53 60.78,57.61 61.8,56.59 D43.2 | D43.1 66.75,50.37 v66.75,47.57 | D36.1 140.78,48.83 139.27,47.32 v139.27,36.78 | v101.68,40.84 101.68,37.8 104.6,34.87 107.9,34.87 109.68,33.1 118.57,33.1 120.22,31.45 124.16,31.45 125.81,29.79 v139.27,29.79 164.29,29.79 164.67,29.41 174.7,29.41 177.88,26.24 189.56,26.24 193.62,30.3 v193.62,30.43
VLED_BANK3  (via drill 0.3)
  Top 0.254: Q4.3 196.21,43.38 197.31,43.38 198.01,44.08 C9.1
  Top 0.381: v16.97,51.77 16.97,48.73 C40.1
  Top 0.406: v6.3,64.08 6.43,63.96 13.79,63.96 16.97,60.78 v16.97,51.77 | v44.65,52.02 49.99,46.69 v68.66,46.69 69.93,46.69 73.1,43.51 v90.63,43.51 | v148.03,61.29 v156.29,61.29 | v105.11,69.93 104.6,70.43 102.57,70.43 102.44,70.56 101.68,70.56 101.17,70.05 v96.85,70.05 | v98.37,60.91 v96.34,60.91
  Top 0.508: v90.63,43.51 93.8,40.34 94.31,40.34 v94.82,39.83 | v123.27,37.67 v123.27,30.56 v123.27,25.1 | v180.67,24.21 181.18,24.71 181.18,26.37 181.94,27.13 v181.94,30.18 | Q4.3 196.16,42.24 v196.48,41.92 198.13,41.92 199.47,40.59 199.47,26.87 197.82,25.22 v197.82,23.83 | v141.81,25.1 v141.81,36.78 | v6.3,67.13 6.43,67.26 12.78,67.26 14.94,69.42 14.94,73.23 11.89,76.28 6.68,76.28 v6.43,76.53
  Bottom 0.406: D63.3 6.95,78.7 D63.2 6.95,77.4 D63.1 7.05,77.28 v6.43,76.53 | v6.3,67.13 6.43,66.98 D64.3 6.95,66.26 D64.2 6.95,64.96 D64.1 7.05,64.83 v6.3,64.08 | D58.3 68.26,44.51 D58.2 68.26,45.81 D58.1 68.16,46.19 v68.66,46.69 | 90.52,43.62 v90.63,43.51 90.63,44.53 D59.3 90.62,44.64 D59.2 90.62,45.94 D59.1 90.5,46.05 90.5,47.19 95.2,51.89 95.2,55.32 98.37,58.5 v98.37,60.91 | D61.1 98.01,37.3 D61.2 96.71,37.3 D61.3 95.98,37.4 94.82,38.56 v94.82,39.83 | D57.3 119.83,29.27 D57.2 119.83,30.57 D57.1 123.15,30.67 v123.27,30.56 | D60.1 127.22,37.3 D60.2 125.92,37.3 D60.3 | D56.1 140.68,44.51 D56.2 140.68,45.81 D56.3 140.79,45.93 140.79,46.43 147.14,52.78 147.14,56.21 148.03,57.1 v148.03,61.29 | D50.2 149.57,23.31 D50.3 | D50.2 148.27,23.31 D50.1 | 148.92,25.1 D50.2 | D54.2 163.54,23.31 D54.3 | D54.2 162.24,23.31 D54.1 | 162.89,25.1 D54.2 | D49.1 192.24,14.03 D49.2 192.24,15.33 D49.3 | D53.3 199.83,21.81 D53.2 201.13,21.81 D53.1 | D55.3 155.16,72.48 D55.2 155.16,71.18 D55.1 155.26,69.81 156.29,68.78 v156.29,61.29 | D62.3 103.59,72.48 D62.2 103.59,71.18 D62.1 103.69,70.7 104.47,69.93 v105.11,69.93 | v96.85,70.05 96.47,70.05 95.83,69.42 95.83,63.32 96.34,62.81 v96.34,60.91 | D51.3 177.48,37.3 D51.2 178.78,37.3 D51.1 181.93,34.35 v181.94,30.18 | D52.1 193.74,45.94 D52.2 193.74,44.64 D52.3 | v16.97,51.77 44.4,51.77 v44.65,52.02
  Bottom 0.508: 125.8,37.41 D60.3 125.57,37.4 125.3,37.67 v123.27,37.67 | D49.3 192.34,16.7 192.35,16.71 192.35,22.81 | D61.1 98.52,37.4 101.8,34.11 107.52,34.11 109.3,32.33 118.06,32.33 D57.1 | v196.48,41.92 193.87,44.54 D52.3 | D53.3 199.72,21.92 198.83,21.92 197.82,22.94 | 192.35,22.81 190.96,24.21 v180.67,24.21 175.46,24.21 174.57,25.1 162.89,25.1 148.92,25.1 v141.81,25.1 v123.27,25.1 | 192.35,22.81 197.69,22.81 197.82,22.94 | D56.1 140.65,37.94 v141.81,36.78 | 197.82,22.94 v197.82,23.83
XLAT  (via drill 0.3)
  Top 0.254: U1.30 156.4,46.32 157.05,45.67 158.06,45.67 158.45,45.29 v158.95,45.29 164.03,45.29 168.1,41.22 168.1,40.34 169.11,39.32 v179.91,39.32 | U1.26 154.4,46.2 154.13,45.92 154.13,45.67 v153.75,45.29 153.75,44.4 153.24,43.89 136.73,43.89 132.92,40.08 119.84,40.08 v118.06,41.86 | U2.30 106.24,47.33 106.76,46.81 107.65,46.81 v108.15,46.3 108.15,45.16 108.53,44.78 111.2,44.78 v113.49,47.07 | v103.07,47.45 103.71,47.45 104.24,47.98 U2.26 | 180.21,73.66 JP7.34 180.34,73.66 180.92,74.24 v182.19,74.24
  Bottom 0.254: v108.15,46.3 104.22,46.3 v103.07,47.45 | v182.19,74.24 182.58,73.86 182.58,70.43 182.45,70.31 182.45,60.15 183.72,58.88 183.72,54.18 180.42,50.88 180.42,42.62 179.91,42.11 v179.91,39.32 | v113.49,47.07 113.49,45.54 117.17,41.86 v118.06,41.86 | v153.75,45.29 153.75,43.51 154.51,42.75 156.41,42.75 v158.95,45.29

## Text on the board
Top: Top | 2
Bottom: Bottom | 3
tPlace: COLORIMETER | LIGHT SENSOR | PROXIMITY | I2C: 0x44 | AUDIO AMP | THERMOMETER | Hygrometer | I2C: 0x40 | ACCELEROMETER | BAROMETER | I2C: 0x19 | MAGNETOMETER | I2C: 0x77 | I2C: 0x1E
Holes: DRILL PLAN | SYM | SIZE | TOL. | CNT | PLATE | 0.012 in | +/-0.003 in | 504 | Yes | 0.126 in | +/-0.003 in | 3 | 0 | Two of these mark the endpoints of a slot. | TOTAL | 507 | 504 | Drill file will contain one extra of | each drill, placed in above diagram. | Drills and Milling | 4
Milling: 0.128" x 0.126" LxW SLOT, NONPLATED
Document: Copyright (C) 2012 The Android Open Source Project | This work is licensed under the Creative Commons | Attribution-ShareAlike 3.0 Unported License. To view a copy of this | license, visit http://creativecommons.org/licenses/by-sa/3.0/ or send | a letter to Creative Commons, 171 Second Street, Suite 300, San | NOTE: HOLE SIZES AND COPPER WEIGHT ARE FINISHED SIZES | Francisco, California, 94105, USA. | ADK 2012 LED | of 4 | REV A
Reference: NOTES: | 1. MATERIAL: MAKE FROM EPOXY GLASS (NEMA-GR-FR4), | COPPER CLAD LAMINATE WITH 1.7 MIL COPPER ON | OUTER LAYERS. | 2 LAYERS, RoHS COMPATIBLE | NONPLATED HOLE | 2. PLATING | A. APPLY BLUE SOLDER MASK OVER BARE COPPER (SMOBC) | WITH LIQUID PHOTO-IMAGEABLE SOLDERMASK | B. ENIG FINISH FOR EXPOSED PADS | 3. SILKSCREEN TOP SIDE WITH WHITE NON-CONDUCTIVE INK | SILKSCREEN BOTTOM SIDE WITH WHITE NON-CONDUCTIVE INK | 4. PLACE PCB VENDOR, UL94V0 CODE APPROX. WHERE SHOWN | ON BOTTOM SILKSCREEN | 5. NO INK STAMPS ON THE TOP OF THE BOARD. | STACKUP: (0.065" +/- 10% OVERALL THICKNESS) | Top Silkscreen | Top Soldermask (0.8 mil) | Top Copper (0.7 mil + 1 mil plate) | FR4 (59 mil) | Bottom Copper (0.7 mil + 1 mil plate) | Bottom Soldermask (0.8 mil) | Bottom Silkscreen | 4. | Notes | 1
